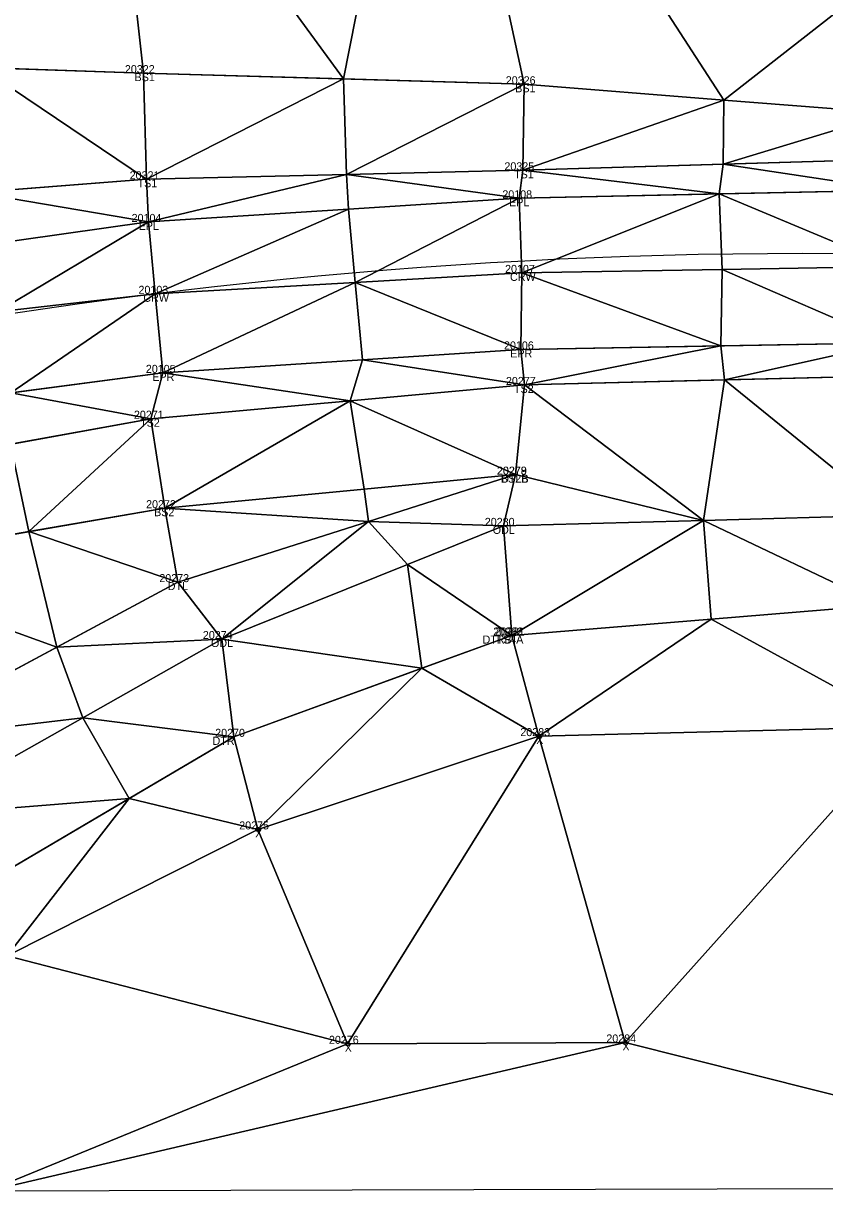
# Model space of a CAD drawing. Extents: x 1966740 to 1969291, y 1117379 to 1118460.
# Drawn here: x 1967997 to 1968097.1, y 1117812.4 to 1117960.2 of the extents above; entities that cross this region are included whole.
import ezdxf

# ---------------------------------------------------------------- set-up
doc = ezdxf.new("R2010")
doc.units = 0
for name, color, linetype in [('Level 1', 7, 'Continuous'), ('Level 10', 7, 'Continuous'), ('Level 3', 7, 'Continuous'), ('Level 30', 7, 'Continuous'), ('Level 35', 7, 'Continuous'), ('Level 50', 7, 'Continuous'), ('Level 52', 7, 'Continuous'), ('Level 53', 7, 'Continuous'), ('Level 56', 7, 'Continuous'), ('Level 6', 7, 'Continuous'), ('Level 60', 7, 'Continuous'), ('Level 61', 7, 'Continuous'), ('Level 62', 7, 'Continuous')]:
    doc.layers.add(name, color=color, linetype=linetype)

msp = doc.modelspace()

# ---------------------------------------------------------------- linework, layer by layer
at = {"layer": 'Level 1'}
msp.add_arc((1968094.39, 1117277.53), 653.93, 87.72663, 111.99584, dxfattribs=at)
at = {"layer": 'Level 10'}
for points in [[(1967872.82, 1117824.49), (1967892.16, 1117820.53), (1967923.08, 1117840.53), (1967966.02, 1117865.44), (1967979.17, 1117870.44), (1968016.32, 1117890.41), (1968058.49, 1117903.84)], [(1967873.55, 1117813.3), (1967887.27, 1117810.69), (1967931.74, 1117824.33), (1967977.85, 1117844.69), (1967988.67, 1117850.69), (1968023.3, 1117871.08), (1968058.02, 1117883.74)]]:
    msp.add_lwpolyline(points, dxfattribs=at)
at = {"layer": 'Level 3'}
for points in [[(1967966.69, 1117955.54), (1968012.01, 1117954.01), (1968059.56, 1117952.62), (1968105.42, 1117949)], [(1967874.77, 1117908.42), (1967879.51, 1117916.91), (1967881.27, 1117924.39), (1967885.24, 1117929.22), (1967913.7, 1117935.63), (1967966.11, 1117937.12), (1968012.39, 1117940.75), (1968059.42, 1117941.87), (1968105.44, 1117943.27), (1968158.32, 1117942.95), (1968212.48, 1117942.1), (1968371.25, 1117933.41), (1968422.85, 1117933.68), (1968531.49, 1117931.42)], [(1967878.98, 1117895.46), (1967875.66, 1117903.48), (1967919.49, 1117917.47), (1967966.4, 1117928.95), (1968012.66, 1117935.42), (1968058.94, 1117938.37), (1968105.99, 1117939.39), (1968158.7, 1117938.56), (1968212.05, 1117937.21), (1968318.79, 1117933.28), (1968422.76, 1117929.93), (1968530.54, 1117925.7)], [(1967878.98, 1117895.46), (1967922.07, 1117909.4), (1967968.89, 1117921.38), (1968013.49, 1117926.44), (1968059.29, 1117929.05), (1968105.63, 1117929.86), (1968159.12, 1117928.97), (1968212.65, 1117927.25), (1968318.5, 1117923.95), (1968422.42, 1117919.39), (1968529.36, 1117916.3)], [(1967878.98, 1117895.46), (1967883.11, 1117885.63), (1967924.99, 1117899.59), (1967970.68, 1117910.78), (1968014.42, 1117916.56), (1968059.13, 1117919.49), (1968105.39, 1117920.31), (1968159.16, 1117919.37), (1968212.5, 1117917.97), (1968317.55, 1117914.44), (1968421.52, 1117910.75), (1968527.82, 1117906.41)], [(1967884.1, 1117882.92), (1967891.06, 1117879.24), (1967898.84, 1117879.11), (1967924.17, 1117888.04), (1967954.33, 1117900.3), (1967970.81, 1117903.15), (1968012.93, 1117910.83), (1968059.62, 1117915.05), (1968105.25, 1117916.2), (1968157.57, 1117912.09), (1968210.74, 1117910.77), (1968320.32, 1117907.54), (1968423.18, 1117904.83), (1968528.99, 1117899.6)], [(1967864, 1117905.28), (1967874.64, 1117878.97), (1967881.18, 1117873.82), (1967887.49, 1117871.9), (1967896.22, 1117872.02), (1967926.22, 1117878.93), (1967959.79, 1117889.45), (1967973.08, 1117892.46), (1968014.67, 1117899.65), (1968058.49, 1117903.84)], [(1968058.02, 1117883.74), (1968104.17, 1117887.52), (1968156.67, 1117888.05), (1968209.1, 1117889.3), (1968320.79, 1117888.13), (1968422.17, 1117888.28), (1968528.68, 1117880.51)]]:
    msp.add_lwpolyline(points, dxfattribs=at)
at = {"layer": 'Level 30'}
for centre in [(1968061.4, 1117871.17), (1968026.29, 1117859.51), (1968037.48, 1117832.72), (1968072.17, 1117832.89)]:
    msp.add_circle(centre, 0.25, dxfattribs=at)
at = {"layer": 'Level 35'}
for points in [[(1968007.64, 1117993.49), (1968047.69, 1118007.46), (1968037, 1117953.28)], [(1968037, 1117953.28), (1968047.69, 1118007.46), (1968059.56, 1117952.62)], [(1968047.69, 1118007.46), (1968106.63, 1117967.98), (1968084.49, 1117950.65)], [(1968047.69, 1118007.46), (1968084.49, 1117950.65), (1968059.56, 1117952.62)], [(1967991.67, 1117954.7), (1968007.64, 1117993.49), (1968012.01, 1117954.01)], [(1968007.64, 1117993.49), (1968037, 1117953.28), (1968012.01, 1117954.01)], [(1968084.49, 1117950.65), (1968106.63, 1117967.98), (1968105.42, 1117949)], [(1967991.03, 1117939.08), (1967991.67, 1117954.7), (1968012.39, 1117940.75)], [(1967991.67, 1117954.7), (1968012.01, 1117954.01), (1968012.39, 1117940.75)], [(1968012.01, 1117954.01), (1968037, 1117953.28), (1968012.39, 1117940.75)], [(1968012.39, 1117940.75), (1968037, 1117953.28), (1968037.38, 1117941.35)], [(1968037, 1117953.28), (1968059.56, 1117952.62), (1968037.38, 1117941.35)], [(1968037.38, 1117941.35), (1968059.56, 1117952.62), (1968059.42, 1117941.87)], [(1968059.42, 1117941.87), (1968059.56, 1117952.62), (1968084.49, 1117950.65)], [(1968059.42, 1117941.87), (1968084.49, 1117950.65), (1968084.41, 1117942.63)], [(1968084.41, 1117942.63), (1968084.49, 1117950.65), (1968105.42, 1117949)], [(1968084.41, 1117942.63), (1968105.42, 1117949), (1968105.44, 1117943.27)], [(1968037.38, 1117941.35), (1968059.42, 1117941.87), (1968058.94, 1117938.37)], [(1968058.94, 1117938.37), (1968059.42, 1117941.87), (1968083.94, 1117938.91)], [(1968059.42, 1117941.87), (1968084.41, 1117942.63), (1968083.94, 1117938.91)], [(1968083.94, 1117938.91), (1968084.41, 1117942.63), (1968105.99, 1117939.39)], [(1968084.41, 1117942.63), (1968105.44, 1117943.27), (1968105.99, 1117939.39)], [(1967991.03, 1117939.08), (1968012.39, 1117940.75), (1968012.66, 1117935.42)], [(1968012.39, 1117940.75), (1968037.38, 1117941.35), (1968012.66, 1117935.42)], [(1968012.66, 1117935.42), (1968037.38, 1117941.35), (1968037.61, 1117937.01)], [(1968037.38, 1117941.35), (1968058.94, 1117938.37), (1968037.61, 1117937.01)], [(1967991.03, 1117939.08), (1968012.66, 1117935.42), (1967991.16, 1117932.41)], [(1968058.94, 1117938.37), (1968083.94, 1117938.91), (1968059.29, 1117929.05)], [(1968059.29, 1117929.05), (1968083.94, 1117938.91), (1968084.29, 1117929.49)], [(1968083.94, 1117938.91), (1968105.99, 1117939.39), (1968105.63, 1117929.86)], [(1968083.94, 1117938.91), (1968105.63, 1117929.86), (1968084.29, 1117929.49)], [(1968037.61, 1117937.01), (1968058.94, 1117938.37), (1968038.45, 1117927.86)], [(1968038.45, 1117927.86), (1968058.94, 1117938.37), (1968059.29, 1117929.05)], [(1968012.66, 1117935.42), (1968037.61, 1117937.01), (1968013.49, 1117926.44)], [(1968013.49, 1117926.44), (1968037.61, 1117937.01), (1968038.45, 1117927.86)], [(1967991.16, 1117932.41), (1968012.66, 1117935.42), (1967993.73, 1117924.19)], [(1967993.73, 1117924.19), (1968012.66, 1117935.42), (1968013.49, 1117926.44)], [(1968038.45, 1117927.86), (1968059.29, 1117929.05), (1968059.13, 1117919.49)], [(1968059.13, 1117919.49), (1968059.29, 1117929.05), (1968084.13, 1117919.93)], [(1968059.29, 1117929.05), (1968084.29, 1117929.49), (1968084.13, 1117919.93)], [(1968084.13, 1117919.93), (1968084.29, 1117929.49), (1968105.39, 1117920.31)], [(1968084.29, 1117929.49), (1968105.63, 1117929.86), (1968105.39, 1117920.31)], [(1968013.49, 1117926.44), (1968038.45, 1117927.86), (1968014.42, 1117916.56)], [(1968014.42, 1117916.56), (1968038.45, 1117927.86), (1968039.37, 1117918.19)], [(1968038.45, 1117927.86), (1968059.13, 1117919.49), (1968039.37, 1117918.19)], [(1967993.73, 1117924.19), (1968013.49, 1117926.44), (1967995.46, 1117914.05)], [(1967995.46, 1117914.05), (1968013.49, 1117926.44), (1968014.42, 1117916.56)], [(1968059.13, 1117919.49), (1968084.13, 1117919.93), (1968059.62, 1117915.05)], [(1968059.62, 1117915.05), (1968084.13, 1117919.93), (1968084.61, 1117915.68)], [(1968084.13, 1117919.93), (1968105.39, 1117920.31), (1968084.61, 1117915.68)], [(1968084.61, 1117915.68), (1968105.39, 1117920.31), (1968105.25, 1117916.2)], [(1968014.42, 1117916.56), (1968039.37, 1117918.19), (1968037.83, 1117913.08)], [(1968037.83, 1117913.08), (1968039.37, 1117918.19), (1968059.62, 1117915.05)], [(1968039.37, 1117918.19), (1968059.13, 1117919.49), (1968059.62, 1117915.05)], [(1967995.46, 1117914.05), (1968014.42, 1117916.56), (1968012.93, 1117910.83)], [(1968012.93, 1117910.83), (1968014.42, 1117916.56), (1968037.83, 1117913.08)], [(1968059.62, 1117915.05), (1968084.61, 1117915.68), (1968081.96, 1117898.12)], [(1968081.96, 1117898.12), (1968084.61, 1117915.68), (1968105.42, 1117898.77)], [(1968084.61, 1117915.68), (1968105.25, 1117916.2), (1968105.42, 1117898.77)], [(1967995.41, 1117907.63), (1967995.46, 1117914.05), (1968012.93, 1117910.83)], [(1968037.83, 1117913.08), (1968059.62, 1117915.05), (1968058.49, 1117903.84)], [(1968058.49, 1117903.84), (1968059.62, 1117915.05), (1968081.96, 1117898.12)], [(1968012.93, 1117910.83), (1968037.83, 1117913.08), (1968014.67, 1117899.65)], [(1968014.67, 1117899.65), (1968037.83, 1117913.08), (1968039.56, 1117902.03)], [(1968037.83, 1117913.08), (1968058.49, 1117903.84), (1968039.56, 1117902.03)], [(1967995.41, 1117907.63), (1968012.93, 1117910.83), (1967997.71, 1117896.72)], [(1967997.71, 1117896.72), (1968012.93, 1117910.83), (1968014.67, 1117899.65)], [(1967973.08, 1117892.46), (1967995.41, 1117907.63), (1967997.71, 1117896.72)], [(1968039.56, 1117902.03), (1968058.49, 1117903.84), (1968040.13, 1117898)], [(1968040.13, 1117898), (1968058.49, 1117903.84), (1968056.97, 1117897.44)], [(1968056.97, 1117897.44), (1968058.49, 1117903.84), (1968081.96, 1117898.12)], [(1968014.67, 1117899.65), (1968039.56, 1117902.03), (1968040.13, 1117898)], [(1967997.71, 1117896.72), (1968014.67, 1117899.65), (1968016.32, 1117890.41)], [(1968014.67, 1117899.65), (1968040.13, 1117898), (1968016.32, 1117890.41)], [(1968016.32, 1117890.41), (1968040.13, 1117898), (1968021.78, 1117883.3)], [(1968021.78, 1117883.3), (1968040.13, 1117898), (1968044.98, 1117892.62)], [(1968040.13, 1117898), (1968056.97, 1117897.44), (1968044.98, 1117892.62)], [(1968056.97, 1117897.44), (1968081.96, 1117898.12), (1968058.02, 1117883.74)], [(1968058.02, 1117883.74), (1968081.96, 1117898.12), (1968082.93, 1117885.78)], [(1968081.96, 1117898.12), (1968105.42, 1117898.77), (1968104.17, 1117887.52)], [(1968081.96, 1117898.12), (1968104.17, 1117887.52), (1968082.93, 1117885.78)], [(1967973.08, 1117892.46), (1967997.71, 1117896.72), (1968001.19, 1117882.28)], [(1967997.71, 1117896.72), (1968016.32, 1117890.41), (1968001.19, 1117882.28)], [(1968044.98, 1117892.62), (1968056.97, 1117897.44), (1968058.02, 1117883.74)], [(1967973.08, 1117892.46), (1968001.19, 1117882.28), (1967979.17, 1117870.44)], [(1968021.78, 1117883.3), (1968044.98, 1117892.62), (1968046.77, 1117879.64)], [(1968044.98, 1117892.62), (1968058.02, 1117883.74), (1968046.77, 1117879.64)], [(1968001.19, 1117882.28), (1968016.32, 1117890.41), (1968021.78, 1117883.3)], [(1968082.93, 1117885.78), (1968104.17, 1117887.52), (1968107.51, 1117872.34)], [(1968058.02, 1117883.74), (1968082.93, 1117885.78), (1968061.4, 1117871.17)], [(1968061.4, 1117871.17), (1968082.93, 1117885.78), (1968107.51, 1117872.34)], [(1968001.19, 1117882.28), (1968021.78, 1117883.3), (1968004.43, 1117873.47)], [(1968004.43, 1117873.47), (1968021.78, 1117883.3), (1968023.3, 1117871.08)], [(1968021.78, 1117883.3), (1968046.77, 1117879.64), (1968023.3, 1117871.08)], [(1968046.77, 1117879.64), (1968058.02, 1117883.74), (1968061.4, 1117871.17)], [(1967979.17, 1117870.44), (1968001.19, 1117882.28), (1968004.43, 1117873.47)], [(1968023.3, 1117871.08), (1968046.77, 1117879.64), (1968026.29, 1117859.51)], [(1968026.29, 1117859.51), (1968046.77, 1117879.64), (1968061.4, 1117871.17)], [(1967979.17, 1117870.44), (1968004.43, 1117873.47), (1967982.67, 1117861.15)], [(1967982.67, 1117861.15), (1968004.43, 1117873.47), (1968010.21, 1117863.37)], [(1968004.43, 1117873.47), (1968023.3, 1117871.08), (1968010.21, 1117863.37)], [(1968010.21, 1117863.37), (1968023.3, 1117871.08), (1968026.29, 1117859.51)], [(1968026.29, 1117859.51), (1968061.4, 1117871.17), (1968037.48, 1117832.72)], [(1968037.48, 1117832.72), (1968061.4, 1117871.17), (1968072.17, 1117832.89)], [(1968061.4, 1117871.17), (1968107.51, 1117872.34), (1968072.17, 1117832.89)], [(1968072.17, 1117832.89), (1968107.51, 1117872.34), (1968144.42, 1117814.73)], [(1967982.67, 1117861.15), (1968010.21, 1117863.37), (1967988.67, 1117850.69)], [(1967988.67, 1117850.69), (1968010.21, 1117863.37), (1967995, 1117843.73)], [(1967995, 1117843.73), (1968010.21, 1117863.37), (1968026.29, 1117859.51)], [(1967995, 1117843.73), (1968026.29, 1117859.51), (1968037.48, 1117832.72)], [(1967992.48, 1117814.29), (1967995, 1117843.73), (1968037.48, 1117832.72)], [(1967992.48, 1117814.29), (1968037.48, 1117832.72), (1968072.17, 1117832.89)], [(1967992.48, 1117814.29), (1968072.17, 1117832.89), (1968144.42, 1117814.73)]]:
    msp.add_lwpolyline(points, close=True, dxfattribs=at)
at = {"layer": 'Level 50'}
for centre in [(1968012.01, 1117954.01), (1968059.56, 1117952.62), (1968059.42, 1117941.87), (1968012.39, 1117940.75), (1968058.94, 1117938.37), (1968012.66, 1117935.42), (1968059.29, 1117929.05), (1968013.49, 1117926.44), (1968059.13, 1117919.49), (1968014.42, 1117916.56), (1968059.62, 1117915.05), (1968012.93, 1117910.83), (1968058.49, 1117903.84), (1968058.49, 1117903.84), (1968014.67, 1117899.65), (1968056.97, 1117897.44), (1968016.32, 1117890.41), (1968021.78, 1117883.3), (1968058.02, 1117883.74), (1968058.02, 1117883.74), (1968023.3, 1117871.08)]:
    msp.add_circle(centre, 0.001, dxfattribs=at)
at = {"layer": 'Level 6'}
msp.add_lwpolyline([(1967868.28, 1117817.14), (1967892.54, 1117814.5), (1967928.24, 1117834.22), (1967973.92, 1117854.29), (1967982.67, 1117861.15), (1968021.78, 1117883.3), (1968056.97, 1117897.44), (1968105.42, 1117898.77), (1968155.9, 1117899.84), (1968209.66, 1117898.76), (1968320.81, 1117895.57), (1968422.79, 1117894.92), (1968528.55, 1117888.35)], dxfattribs=at)

# ---------------------------------------------------------------- texts
at = {"layer": 'Level 52'}
for s, p in [('20283', (1968059.09, 1117871.17)), ('20275', (1968023.97, 1117859.51)), ('20276', (1968035.18, 1117832.72)), ('20284', (1968069.83, 1117832.89))]:
    msp.add_text(s, height=1, dxfattribs=at).set_placement(p)
at = {"layer": 'Level 53'}
for s, p in [('20322', (1968009.69, 1117954.01)), ('BS1', (1968010.9, 1117953.01)), ('20326', (1968057.27, 1117952.62)), ('BS1', (1968058.45, 1117951.62)), ('20325', (1968057.1, 1117941.87)), ('TS1', (1968058.31, 1117940.87)), ('20321', (1968010.29, 1117940.75)), ('TS1', (1968011.28, 1117939.75)), ('20108', (1968056.84, 1117938.37)), ('EPL', (1968057.69, 1117937.37)), ('20104', (1968010.53, 1117935.42)), ('EPL', (1968011.41, 1117934.42)), ('20107', (1968057.18, 1117929.05)), ('CRW', (1968057.8, 1117928.05)), ('20103', (1968011.39, 1117926.44)), ('CRW', (1968012, 1117925.44)), ('20106', (1968057.05, 1117919.49)), ('EPR', (1968057.83, 1117918.49)), ('20105', (1968012.31, 1117916.56)), ('EPR', (1968013.12, 1117915.56)), ('20277', (1968057.29, 1117915.05)), ('TS2', (1968058.3, 1117914.05)), ('20271', (1968010.82, 1117910.83)), ('TS2', (1968011.6, 1117909.83)), ('20278', (1968056.16, 1117903.84)), ('BS2B', (1968056.66, 1117902.84)), ('20272', (1968012.34, 1117899.65)), ('BS2', (1968013.34, 1117898.65)), ('20282', (1968055.7, 1117883.74)), ('TS4A', (1968056.12, 1117882.74))]:
    msp.add_text(s, height=1, dxfattribs=at).set_placement(p)
at = {"layer": 'Level 56'}
for s, p in [('20280', (1968054.65, 1117897.44)), ('ODL', (1968055.64, 1117896.44)), ('20274', (1968019.43, 1117883.3)), ('ODL', (1968020.45, 1117882.3))]:
    msp.add_text(s, height=1, dxfattribs=at).set_placement(p)
at = {"layer": 'Level 60'}
for s, p in [('DTLB', (1968056.71, 1117902.84)), ('DTL', (1968015.04, 1117889.41)), ('DTRB', (1968054.37, 1117882.74)), ('DTR', (1968020.64, 1117870.08))]:
    msp.add_text(s, height=1, dxfattribs=at).set_placement(p)
at = {"layer": 'Level 61'}
for s, p in [('20279', (1968056.18, 1117903.84)), ('20273', (1968013.99, 1117890.41)), ('20281', (1968055.91, 1117883.74)), ('20270', (1968020.97, 1117871.08))]:
    msp.add_text(s, height=1, dxfattribs=at).set_placement(p)
at = {"layer": 'Level 62'}
for p in [(1968061.07, 1117870.17), (1968025.96, 1117858.51), (1968037.15, 1117831.72), (1968071.84, 1117831.89)]:
    msp.add_text('X', height=1, dxfattribs=at).set_placement(p)

doc.saveas('drawing.dxf')
